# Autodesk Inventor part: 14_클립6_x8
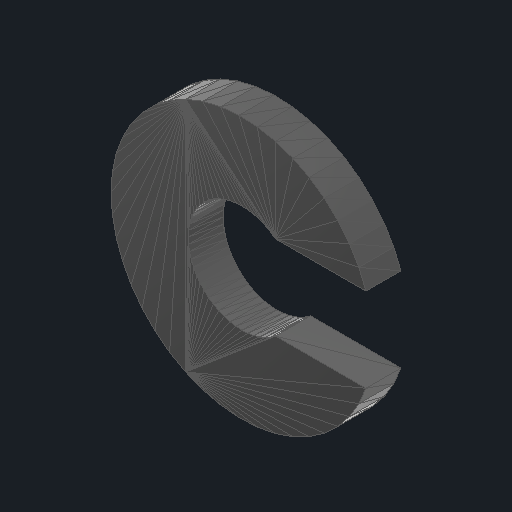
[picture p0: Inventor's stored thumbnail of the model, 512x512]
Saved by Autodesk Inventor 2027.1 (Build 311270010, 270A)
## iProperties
Created: 2026-11
Part Number: 14_클립6_x8
Material: 일반
Document SubType Name: Modeling
Designer: djshs
Density: 1 g/cm^3
Appearance: 기본값
Author: djshs
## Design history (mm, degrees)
node "14_클립6_x8"
  node "MeshFeature1"
